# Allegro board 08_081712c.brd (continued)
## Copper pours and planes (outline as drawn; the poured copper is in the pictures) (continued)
DGND on L8_SIG (solid shape): 237.92,84.72 238,84.68 238.01,84.59 238,84.52 237.99,84.45 238.4,84.05 238.81,84.45 238.8,84.52 238.78,84.59 238.8,84.68 238.88,84.72 244.93,84.72 245.02,84.66 245,84.55 244.61,84.15 239.79,84.15 239.67,84.13 239.56,84.06 238.22,82.71 238.15,82.61 238.12,82.49 238.12,80.21 238.15,80.08 238.22,79.98 238.33,79.87 238.35,79.76 238.26,79.69 237.75,79.69 237.6,79.85 237.57,79.94 237.64,80.02 237.87,80.16 237.95,80.41 237.84,80.7 237.55,80.82 237.43,80.8 237.33,80.75 237.23,80.75 237.17,80.84 237.17,81.48 237.23,81.57 237.33,81.57 237.43,81.52 237.55,81.5 237.95,81.91 237.55,82.32 237.43,82.3 237.33,82.25 237.23,82.25 237.17,82.34 237.17,84.22 237.67,84.72
DGND on L8_SIG (solid shape): 205.14,77.42 205.77,77.16 206.41,77.42 207.04,77.16 207.68,77.42 208.31,77.16 208.95,77.42 209.58,77.16 210.22,77.42 210.25,77.4 210.41,77.29 210.58,77.21 210.65,77.13 210.62,77.04 207.34,73.75 207.22,73.73 207.16,73.83 207.16,73.86 206.47,74.15 206.76,73.45 206.78,73.45 206.88,73.39 206.86,73.28 205.86,72.28 199.42,72.28 199.33,72.34 199.35,72.45 204.14,77.24 204.17,77.23 204.34,77.18 204.5,77.16 204.83,77.23 205.1,77.4
DGND on L8_SIG (solid shape): 297.64,103.58 297.73,103.54 297.74,103.45 297.73,103.4 297.71,103.35 296.93,102.56 296.86,102.46 296.84,102.34 296.84,99.83 292.38,95.36 253.95,95.36 253.83,95.34 253.72,95.27 244.55,86.09 237.65,86.09 237.56,86.16 237.58,86.27 238.7,87.39 238.99,87.39 239.08,87.34 239.08,87.23 239.04,87.13 239.02,87.02 239.43,86.62 239.83,87.02 239.82,87.13 239.78,87.23 239.77,87.34 239.86,87.39 244.04,87.39 244.16,87.41 244.27,87.48 252.46,95.67 290.53,95.67 290.65,95.69 290.75,95.76 295.75,100.76 295.85,100.79 295.92,100.72 296.07,100.52 296.3,100.45 296.59,100.57 296.71,100.85 296.63,101.09 296.43,101.24 296.37,101.31 296.4,101.41 296.44,101.45 296.51,101.55 296.53,101.68 296.53,102.62 296.6,102.74 296.62,102.87 296.5,103.16 296.21,103.28 296.2,103.28 296.11,103.34 296.13,103.45 296.26,103.58
DGND on L8_SIG (solid shape): 239.32,101.48 239.32,98.59 239.35,98.47 239.42,98.36 240.12,97.66 240.12,97.56 240.06,97.47 239.95,97.49 239.73,97.71 239.62,97.78 239.5,97.81 239.16,97.81 238.47,98.5 238.44,98.6 238.51,98.67 238.73,98.82 238.81,99.06 238.69,99.35 238.4,99.47 238.16,99.39 238.01,99.17 237.94,99.1 237.84,99.13 236.44,100.53 236.33,100.6 236.21,100.63 233.02,100.63 232.92,100.69 232.94,100.8 233.72,101.57 233.75,101.54 233.87,101.47 234.01,101.45 234.42,101.85 234.01,102.26 233.96,102.26 233.91,102.25 233.82,102.27 233.78,102.35 233.78,102.36 233.82,102.44 233.91,102.46 233.96,102.45 234.01,102.45 234.3,102.57 234.42,102.85 234.33,103.11 234.09,103.25 234.02,103.32 234.04,103.42 234.07,103.45 234.08,103.45 234.32,103.59 234.42,103.85 234.42,103.91 234.41,103.96 234.42,104.04 234.5,104.08 236.72,104.08
DGND on L8_SIG (solid shape): 306.51,106.77 306.58,106.67 306.5,106.58 306.29,106.43 306.21,106.19 306.62,105.78 307.02,106.19 307.02,106.2 307.05,106.28 307.12,106.31 307.85,106.31 307.94,106.25 307.92,106.14 307.85,106.02 307.82,105.87 308.23,105.47 308.64,105.87 308.61,106.02 308.53,106.14 308.52,106.25 308.61,106.31 308.86,106.31 310.3,104.87 310.3,104.82 310.25,104.73 310.15,104.72 310.07,104.75 309.98,104.76 309.84,104.74 309.72,104.67 303.92,104.67 303.8,104.74 303.66,104.76 303.53,104.74 303.42,104.68 303.4,104.67 303.27,104.67 302.33,105.61 302.23,105.68 302.11,105.7 296.92,105.7 296.82,105.77 296.85,105.88 296.95,106.02 296.99,106.19 296.58,106.59 296.18,106.19 296.21,106.02 296.31,105.88 296.34,105.77 296.25,105.7 296.12,105.7 295.22,106.6 295.2,106.71 295.3,106.77
DGND on L8_SIG (solid shape): 18.43,102.06 18.54,102.08 18.61,101.98 18.61,101.1 5.24,87.73 5.17,87.62 5.14,87.5 5.14,65.28 5.17,65.16 5.24,65.05 17.04,53.25 17.04,33.37 16.97,33.25 16.95,33.12 16.96,33.02 17,32.92 17.01,32.84 16.96,32.78 16.91,32.75 16.86,32.71 16.68,32.52 16.66,32.52 16.41,32.38 16.31,32.12 16.43,31.83 16.72,31.71 16.79,31.68 16.94,31.33 17.23,31.21 17.63,31.62 17.23,32.03 17.18,32.02 17.13,32.08 17.22,32.17 20.8,32.17 20.93,32.19 21.03,32.26 28.61,39.84 28.68,39.95 28.7,40.07 28.7,63.68 28.74,63.73 28.81,63.78 28.9,63.75 29.1,63.55 29.1,39.55 16.07,26.53 15.87,26.53 15.78,26.58 15.78,26.69 15.84,26.8 15.85,26.92 15.85,26.99 15.83,27.06 15.83,27.14 15.89,27.19 16.07,27.34 16.14,27.57 16.02,27.86 15.74,27.98 15.49,27.89 15.34,27.68 15.27,27.61 15.18,27.64 14.82,27.99 14.82,54.76 14.8,54.88 14.73,54.98 4.64,65.07 4.64,88.26
DGND on L8_SIG (solid shape): outline of 91 points within 106.31,97.47 122.93,102.54
DGND on L8_SIG (solid shape): outline of 121 points within 205.04,18.95 208.1,27.47
DGND on L8_SIG (solid shape): outline of 303 points within 303.11,100.8 310.3,104.04
DGND on L8_SIG (solid shape): outline of 104 points within 221.69,101.13 233.62,104.15
DGND on L8_SIG (solid shape): outline of 355 points within 131.44,71.67 143.6,81.26
DGND on L8_SIG (solid shape): outline of 101 points within 169.88,60.41 190.9,65.21
DGND on L8_SIG (solid shape): outline of 390 points within 119.81,93.07 132.14,98.63
DGND on L8_SIG (solid shape): outline of 448 points within 66.44,81.1 114.25,99.38
DGND on L8_SIG (solid shape): outline of 434 points within 244.73,76.34 265.87,87.41
DGND on L8_SIG (solid shape): outline of 446 points within 102.75,68.83 122.15,72.81
DGND on L8_SIG (solid shape): outline of 89 points within 172.44,100.63 219.74,102.78
DGND on L8_SIG (solid shape): outline of 742 points within 255.26,58.99 277.13,65.69
DGND on L8_SIG (solid shape): outline of 817 points within 250.55,68.82 272.83,78.07
DGND on L8_SIG (solid shape): outline of 1048 points within 242.85,77.56 320.67,107.48
DGND on L8_SIG (solid shape): outline of 1122 points within 124.18,61.39 171.4,65.21
DGND on L8_SIG (solid shape): outline of 1906 points within 52.34,68.83 143.32,84.39
DGND on L8_SIG (solid shape): outline of 2300 points within 186.86,55.06 253.37,98.86
DGND on L8_SIG (solid shape): outline of 2666 points within 129.34,89.27 295.33,107.77
DGND on L8_SIG (solid shape): outline of 3018 points within 271.21,63.6 362.99,77.66
DGND on L8_SIG (solid shape): outline of 4211 points within 91.21,69.81 216.93,100.13
DGND on TOP: 2.54,194.31 412.75,194.31 412.75,2.54 2.54,2.54 ; 104 cut-outs
DGND on BOTTOM: 217.04,73.28 217.04,70.87 216.79,70.61 215.65,70.61 215.52,70.74 215.52,73.66 215.65,73.79 216.53,73.79
DGND on BOTTOM: 221.61,73.28 221.61,70.87 221.87,70.61 223.01,70.61 223.14,70.74 223.14,73.66 223.01,73.79 222.12,73.79
DGND on BOTTOM: 215.77,84.84 215.77,83.06 218.95,83.06 218.95,84.84
DGND on L2_GND, L4_GND, L5_PWR, L6_PWR, L7_GND, L9_GND: 2.54,194.31 412.75,194.31 412.75,2.54 2.54,2.54
GND_FIELD on BOTTOM (solid shape): outline of 554 points within 126.75,2.54 146.3,15.49
GND_FIELD on BOTTOM (solid shape): outline of 554 points within 253.75,2.54 273.3,15.49
VDDIO on TOP (solid shape): 407.42,105.54 407.29,105.41 405.38,105.41 405.13,105.66 405.13,107.82 405.26,107.95 407.42,107.95
VDDIO on TOP (solid shape): 147.83,36.05 147.83,34.63 147.78,34.58 144.8,34.58 144.8,34.58 144.8,36.1 144.9,36.2 146.29,36.2 146.42,36.32 147.56,36.32
VDDIO on TOP (solid shape): 274.83,36.18 274.83,34.63 274.78,34.58 271.8,34.58 271.8,34.58 271.8,35.97 272.02,36.2 273.29,36.2 273.55,36.45 274.56,36.45
VDDIO on TOP (solid shape): 223.27,111.43 223.27,111.31 223.07,111.11 223.07,111.03 223.07,110.42 223.07,110.29 223.01,110.24 222.25,110.24 222.12,110.11 222.12,109.6 222,109.47 221.61,109.47 221.49,109.6 221.49,111.25 221.68,111.44 223.25,111.44
VDDIO on TOP (solid shape): 300.99,111.43 300.99,111.31 300.79,111.11 300.79,111.03 300.79,110.42 300.79,110.29 300.74,110.24 299.97,110.24 299.85,110.11 299.85,109.6 299.72,109.47 299.34,109.47 299.21,109.6 299.21,111.25 299.4,111.44 300.98,111.44
VDDIO on TOP (solid shape): 16.63,24.11 16.63,22.46 16.44,22.27 14.86,22.27 14.85,22.28 14.85,22.4 15.05,22.6 15.06,22.7 15.06,23.31 15.05,23.42 15.11,23.48 15.87,23.48 15.99,23.6 15.99,24.11 16.12,24.24 16.5,24.24
VDDIO on TOP (solid shape): 384.29,24.11 384.29,22.46 384.1,22.27 382.53,22.27 382.52,22.28 382.52,22.4 382.71,22.6 382.72,22.7 382.72,23.31 382.71,23.42 382.77,23.48 383.53,23.48 383.66,23.6 383.66,24.11 383.79,24.24 384.17,24.24
VDDIO on TOP (solid shape): 229.62,111.43 229.62,111.31 229.42,111.11 229.42,111.03 229.42,110.42 229.42,110.29 229.36,110.24 228.6,110.24 228.47,110.11 228.47,109.6 228.35,109.48 228.23,109.48 228.19,109.47 227.96,109.47 227.84,109.6 227.84,111.25 228.03,111.44 229.6,111.44
VDDIO on TOP (solid shape): 307.34,111.43 307.34,111.31 307.14,111.11 307.14,111.03 307.14,110.42 307.14,110.29 307.09,110.24 306.32,110.24 306.2,110.11 306.2,109.6 306.08,109.48 305.96,109.48 305.91,109.47 305.69,109.47 305.56,109.6 305.56,111.25 305.75,111.44 307.33,111.44
VDDIO on TOP (solid shape): outline of 85 points within 384.56,113.03 397.13,116.2
VDDIO on TOP: 123.95,102.09 123.95,103.74 124.14,103.93 125.72,103.93 125.73,103.92 125.73,103.8 125.53,103.6 125.53,102.78 125.48,102.72 124.71,102.72 124.59,102.6 124.59,102.09 124.46,101.96 124.08,101.96
VDDIO on TOP: 188.09,84.58 188.09,86.23 188.28,86.42 189.85,86.42 189.86,86.41 189.86,86.29 189.67,86.09 189.67,85.27 189.61,85.22 188.85,85.22 188.72,85.09 188.72,84.58 188.59,84.45 188.21,84.45
VDDIO on TOP: 236.63,28.83 236.63,31.09 236.8,31.27 238.25,31.27 238.48,31.04 238.48,30.48 238.33,30.33 237.77,30.33 237.31,29.87 237.31,28.8 237.24,28.73 236.73,28.73
VDDIO on TOP: 182.59,121.54 182.59,122.76 180.83,122.76 180.83,122.28 182.08,122.28 182.08,121.54 182.21,121.41 182.46,121.41
VDDIO on TOP: 112.71,102.15 112.71,103.68 112.97,103.93 114.54,103.93 114.55,103.92 114.55,103.8 114.36,103.6 114.36,102.78 114.3,102.72 113.54,102.72 113.41,102.6 113.41,102.09 113.28,101.96 112.9,101.96
VDDIO on BOTTOM: 188.09,82.66 188.09,81.01 188.29,80.82 189.86,80.82 189.87,80.83 189.87,80.95 189.68,81.14 189.68,81.97 189.62,82.02 188.86,82.02 188.73,82.15 188.73,82.66 188.6,82.78 188.22,82.78
VDDIO on BOTTOM: 120.85,102.19 120.85,103.68 120.58,103.95 119,103.95 118.99,103.94 118.99,103.82 119.19,103.62 119.19,102.8 119.25,102.74 120.01,102.74 120.13,102.62 120.13,102.11 120.26,101.98 120.64,101.98
VDDIO on L5_PWR: 388.8,119.79 388.8,80.26 319.15,80.26 319.15,64.52 388.8,64.52 388.8,20.19 228.5,20.19 228.5,40.18 213.64,40.18 213.64,61.26 204.09,61.26 204.09,65.33 189.59,65.33 189.59,20.19 9.65,20.19 9.65,119.96 37.52,119.96 37.52,103.05 157.77,103.05 177.15,122.43 186.17,122.43 188.81,119.79
(no net) on TOP: 220.34,15.56 220.34,13.78 220.6,13.53 220.6,13.14 219.77,13.14 219.46,13.46 219.46,13.84 219.2,14.1 218.69,14.1 218.57,14.22 218.57,15.37 218.88,15.68 220.22,15.68
(no net) on TOP: 221.49,113.41 221.49,112.01 221.7,111.8 223.07,111.8 223.07,112.47 223.01,112.52 222.25,112.52 222.12,112.65 222.12,113.41 222,113.54 221.61,113.54
(no net) on TOP: 144.75,42.36 144.75,44.43 144.84,44.52 147.7,44.52 147.79,44.43 147.79,42.31 147.79,42.3 144.81,42.3
(no net) on TOP: 16.63,24.11 16.63,22.46 16.44,22.27 14.86,22.27 14.85,22.28 14.85,22.4 15.05,22.6 15.05,23.42 15.11,23.48 15.87,23.48 15.99,23.6 15.99,24.11 16.12,24.24 16.5,24.24
(no net) on TOP: 401.07,131.45 401.07,131.19 407.91,131.19 408.43,131.71 408.43,133.22 407.54,134.11 406.02,134.11 404.88,132.97 403.35,132.97 402.84,132.46 402.84,131.7 402.59,131.45
(no net) on TOP: 345.06,190.88 345.06,185.42 345.82,184.66 355.22,184.66 355.85,184.02 358.78,184.02 359.03,184.28 359.03,190.63 358.27,191.39 345.57,191.39
(no net) on TOP: 395.61,175.64 395.61,175.01 395.68,174.93 397.76,174.93 397.76,175.26 396.49,175.26 396.11,175.64
(no net) on TOP: 227.84,109.6 227.84,111.25 228.03,111.44 229.6,111.44 229.62,111.43 229.62,111.31 229.42,111.11 229.42,110.29 229.36,110.24 228.6,110.24 228.47,110.11 228.47,109.6 228.35,109.47 227.96,109.47
(no net) on TOP: 264.62,46.02 262.95,46.02 262.95,47.64 263.28,47.97 264.28,47.97 264.62,47.64
(no net) on TOP: 392.56,112.01 397.13,112.01 397.13,110.74 395.1,110.74 395.1,108.97 395.48,108.58 397.76,108.58 397.76,108.33 394.46,108.33 394.46,110.74 392.56,110.74
(no net) on TOP: 401.07,174.62 401.07,174.37 405.64,174.37 406.02,174.75 406.02,175.9 405.77,176.15 403.35,176.15 402.84,175.64 402.84,174.88 402.59,174.62
(no net) on TOP: 305.56,109.6 305.56,111.25 305.75,111.44 307.33,111.44 307.34,111.43 307.34,111.31 307.14,111.11 307.14,110.29 307.09,110.24 306.32,110.24 306.2,110.11 306.2,109.6 306.07,109.47 305.69,109.47
(no net) on TOP: 395.61,155.19 395.61,154.56 395.68,154.48 397.76,154.48 397.76,154.81 396.49,154.81 396.11,155.19
(no net) on TOP: 384.56,182.25 384.56,180.09 397.13,180.09 397.13,182.25
(no net) on TOP: 274.83,48.22 274.83,50.1 274.55,50.38 272.01,50.38 271.79,50.15 271.79,48.18 271.79,48.17 274.78,48.17
(no net) on TOP: 402.46,114.05 402.46,111.25 404.37,111.25 404.37,114.05
(no net) on TOP: 272.67,18.92 272.67,24.51 272.54,24.64 269.37,24.64 268.86,24.13 268.86,23.11 267.84,22.1 267.84,20.32 267.08,19.56 259.97,19.56 259.21,20.32 259.21,22.1 258.19,23.11 258.19,24.13 257.68,24.64 254.51,24.64 254.38,24.51 254.38,18.92 255.14,18.16 271.91,18.16
(no net) on TOP: 362.97,183.26 362.97,180.34 363.86,179.45 374.4,179.45 375.16,180.21 375.16,182.88 374.52,183.52 363.22,183.52
(no net) on TOP: 230.76,20.51 232.28,20.51 232.28,20.26 232.03,20 232.03,18.86 231.77,18.61 224.54,18.61 224.54,19.62 229.87,19.62
(no net) on TOP: 221.49,109.6 221.49,111.25 221.68,111.44 223.25,111.44 223.27,111.43 223.27,111.31 223.07,111.11 223.07,110.29 223.01,110.24 222.25,110.24 222.12,110.11 222.12,109.6 222,109.47 221.61,109.47
(no net) on TOP: 401.07,154.18 401.07,153.92 407.79,153.92 408.43,154.57 408.43,155.96 407.54,156.84 406.02,156.84 404.88,155.7 403.35,155.7 402.84,155.19 402.84,154.43 402.59,154.18
(no net) on TOP: 261.03,43.86 259.51,43.86 259.21,44.15 259.21,45.3 259.46,45.54 261.03,45.54
(no net) on TOP: 137.62,46.02 135.95,46.02 135.95,47.64 136.28,47.97 137.28,47.97 137.62,47.64
(no net) on TOP: 405.13,130.68 405.13,128.52 405.38,128.27 407.29,128.27 407.42,128.4 407.42,130.81 405.26,130.81
(no net) on TOP: 395.61,109.6 395.61,108.97 395.68,108.89 397.76,108.89 397.76,109.22 396.49,109.22 396.11,109.6
(no net) on TOP: 402.46,180.09 402.46,177.29 404.37,177.29 404.37,180.09
(no net) on TOP: 145.67,18.92 145.67,24.51 145.54,24.64 142.37,24.64 141.86,24.13 141.86,23.11 140.84,22.1 140.84,20.32 140.08,19.56 132.97,19.56 132.21,20.32 132.21,22.1 131.19,23.11 131.19,24.13 130.68,24.64 127.51,24.64 127.38,24.51 127.38,18.92 128.14,18.16 144.91,18.16
(no net) on TOP: 384.56,161.8 384.56,159.25 384.93,158.88 388.1,158.88 388.86,159.64 397.13,159.64 397.13,161.8
(no net) on TOP: 231.9,24.45 231.9,20.76 230.76,20.76 230.5,21.02 230.5,23.18 230,23.69 224.54,23.69 224.54,24.7 231.65,24.7
(no net) on TOP: 139.4,43.11 139.4,44.78 141.11,44.78 141.36,44.54 141.36,43.4 141.07,43.11
(no net) on TOP: 221.87,11.62 224.03,11.62 224.16,11.49 224.16,10.6 224.41,10.35 229.23,10.35 229.23,11.11 228.47,11.87 221.87,11.87
(no net) on TOP: 134.03,43.86 132.51,43.86 132.21,44.15 132.21,45.3 132.46,45.54 134.03,45.54
(no net) on TOP: 405.13,107.82 405.13,105.66 405.38,105.41 407.29,105.41 407.42,105.54 407.42,107.95 405.26,107.95
(no net) on TOP: 299.21,113.41 299.21,112.01 299.43,111.8 300.79,111.8 300.79,112.47 300.74,112.52 299.97,112.52 299.85,112.65 299.85,113.41 299.72,113.54 299.34,113.54
(no net) on TOP: 401.07,108.58 401.07,108.33 407.79,108.33 408.43,108.98 408.43,110.36 407.54,111.25 406.02,111.25 404.88,110.11 403.35,110.11 402.84,109.6 402.84,108.84 402.59,108.58
(no net) on TOP: 220.6,11.87 220.6,10.99 220.09,10.48 220.09,5.4 219.58,4.89 216.03,4.89 215.52,5.4 215.52,7.3 216.15,7.94 218.31,7.94 218.82,8.45 218.82,11.37 219.33,11.87
(no net) on TOP: 266.4,43.11 266.4,44.78 268.11,44.78 268.36,44.54 268.36,43.4 268.07,43.11
(no net) on TOP: 384.56,139.06 384.56,136.39 384.8,136.14 387.97,136.14 388.74,136.91 397.13,136.91 397.13,139.06
(no net) on TOP: 384.29,20.3 384.29,21.7 384.08,21.91 382.71,21.91 382.71,21.25 382.77,21.19 383.53,21.19 383.66,21.06 383.66,20.3 383.79,20.17 384.17,20.17
(no net) on TOP: 392.56,134.87 397.13,134.87 397.13,133.6 395.1,133.6 395.1,131.83 395.48,131.45 397.76,131.45 397.76,131.19 394.46,131.19 394.46,133.6 392.56,133.6
(no net) on TOP: 402.46,136.91 402.46,134.11 404.37,134.11 404.37,136.91
(no net) on TOP: 384.56,116.2 384.56,113.53 385.05,113.03 387.72,113.03 388.74,114.05 397.13,114.05 397.13,116.2
(no net) on TOP: 229.23,9.59 224.66,9.59 224.66,6.03 225.04,5.65 228.73,5.65 229.23,6.16
(no net) on TOP: 392.56,157.61 397.13,157.61 397.13,156.34 395.1,156.34 395.1,154.56 395.48,154.18 397.76,154.18 397.76,153.92 394.46,153.92 394.46,156.34 392.56,156.34
(no net) on TOP: 384.29,24.11 384.29,22.46 384.1,22.27 382.53,22.27 382.52,22.28 382.52,22.4 382.71,22.6 382.71,23.42 382.77,23.48 383.53,23.48 383.66,23.6 383.66,24.11 383.79,24.24 384.17,24.24
(no net) on TOP: 402.46,159.64 402.46,156.84 404.37,156.84 404.37,159.64
(no net) on TOP: 405.13,173.86 405.13,171.7 405.38,171.45 407.29,171.45 407.42,171.58 407.42,173.99 405.26,173.99
(no net) on TOP: 337.95,190.63 337.95,188.85 337.44,188.34 328.68,188.34 328.04,187.71 328.04,184.15 328.8,183.39 340.87,183.39 341.38,183.9 341.38,190.63 341.12,190.88 338.2,190.88
(no net) on TOP: 395.61,132.46 395.61,131.83 395.68,131.75 397.76,131.75 397.76,132.08 396.49,132.08 396.11,132.46
(no net) on TOP: 147.83,34.63 147.83,36.05 147.56,36.32 146.42,36.32 146.29,36.2 144.9,36.2 144.8,36.1 144.8,34.58 144.8,34.58 147.78,34.58
(no net) on TOP: 305.56,113.41 305.56,112.01 305.78,111.8 307.14,111.8 307.14,112.47 307.09,112.52 306.32,112.52 306.2,112.65 306.2,113.41 306.07,113.54 305.69,113.54
(no net) on TOP: 392.56,178.05 397.13,178.05 397.13,176.78 395.1,176.78 395.1,175.01 395.48,174.62 397.76,174.62 397.76,174.37 394.46,174.37 394.46,176.78 392.56,176.78
(no net) on TOP: 227.96,23.43 229.87,23.43 230.12,23.18 230.12,20.26 229.74,19.88 227.96,19.88 227.71,20.13 227.71,23.18
(no net) on TOP: 360.05,190.75 360.05,186.82 360.43,186.44 367.03,186.44 368.05,187.45 368.05,190.5 367.16,191.39 360.68,191.39
(no net) on TOP: 147.83,48.22 147.83,50.1 147.55,50.38 145.01,50.38 144.79,50.15 144.79,48.18 144.79,48.17 147.78,48.17
(no net) on TOP: 16.63,20.3 16.63,21.7 16.41,21.91 15.05,21.91 15.05,21.25 15.11,21.19 15.87,21.19 15.99,21.06 15.99,20.3 16.12,20.17 16.5,20.17
(no net) on TOP: 405.13,153.42 405.13,151.26 405.38,151 407.29,151 407.42,151.13 407.42,153.54 405.26,153.54
(no net) on TOP: 299.21,109.6 299.21,111.25 299.4,111.44 300.98,111.44 300.99,111.43 300.99,111.31 300.79,111.11 300.79,110.29 300.74,110.24 299.97,110.24 299.85,110.11 299.85,109.6 299.72,109.47 299.34,109.47
(no net) on TOP: 221.87,11.37 223.77,11.37 223.9,11.24 223.9,10.6 223.27,10.6 222.76,11.11 221.87,11.11
(no net) on TOP: 227.84,113.41 227.84,112.01 228.05,111.8 229.42,111.8 229.42,112.47 229.36,112.52 228.6,112.52 228.47,112.65 228.47,113.41 228.35,113.54 227.96,113.54
(no net) on TOP: 274.83,34.63 274.83,36.18 274.56,36.45 273.55,36.45 273.29,36.2 272.02,36.2 271.8,35.97 271.8,34.58 271.8,34.58 274.78,34.58
(no net) on TOP: 271.75,42.36 271.75,44.43 271.84,44.52 274.7,44.52 274.79,44.43 274.79,42.31 274.79,42.3 271.81,42.3
(no net) on BOTTOM: 236.98,72.14 236.98,67.69 239.27,67.69 239.27,72.14
(no net) on BOTTOM: 96.77,59.18 96.77,57.02 96.52,56.77 94.61,56.77 94.49,56.9 94.49,58.67 95.12,59.31 96.65,59.31
(no net) on BOTTOM: 236.35,63.37 231.77,63.37 231.77,62.1 233.81,62.1 233.81,60.32 233.43,59.94 231.14,59.94 231.14,59.69 234.44,59.69 234.44,62.1 236.35,62.1
(no net) on BOTTOM: 2.54,194.31 412.75,194.31 412.75,2.54 2.54,2.54 ; 3 cut-outs
(no net) on BOTTOM: 109.98,72.14 109.98,67.69 112.27,67.69 112.27,72.14
(no net) on BOTTOM: 99.44,65.41 99.44,62.61 97.54,62.61 97.54,65.41
(no net) on BOTTOM: 223.77,59.18 223.77,57.02 223.52,56.77 221.61,56.77 221.49,56.9 221.49,58.67 222.12,59.31 223.65,59.31
(no net) on BOTTOM: 236.35,72.14 236.35,65.41 231.77,65.41 231.77,72.14
(no net) on BOTTOM: 106.3,60.96 106.3,60.32 106.22,60.25 104.14,60.25 104.14,60.58 105.41,60.58 105.79,60.96
(no net) on BOTTOM: 109.35,63.37 104.78,63.37 104.78,62.1 106.81,62.1 106.81,60.32 106.43,59.94 104.14,59.94 104.14,59.69 107.44,59.69 107.44,62.1 109.35,62.1
(no net) on BOTTOM: 233.3,60.96 233.3,60.32 233.22,60.25 231.14,60.25 231.14,60.58 232.41,60.58 232.79,60.96
(no net) on BOTTOM: 227.84,59.94 227.84,59.69 223.01,59.69 223.01,60.96 223.52,61.47 225.55,61.47 226.06,60.96 226.06,60.2 226.31,59.94
(no net) on BOTTOM: 109.35,72.14 109.35,65.41 104.78,65.41 104.78,72.14
(no net) on BOTTOM: 100.84,59.94 100.84,59.69 96.01,59.69 96.01,60.96 96.52,61.47 98.55,61.47 99.06,60.96 99.06,60.2 99.31,59.94
(no net) on BOTTOM: 273.3,2.54 253.75,2.54 253.75,15.49 273.3,15.49
(no net) on BOTTOM: 226.44,65.41 226.44,62.61 224.54,62.61 224.54,65.41
(no net) on BOTTOM: 146.3,2.54 126.75,2.54 126.75,15.49 146.3,15.49
(no net) on L3_SIG, L8_SIG: 2.54,194.31 412.75,194.31 412.75,2.54 2.54,2.54
(no net) on L5_PWR: 190.25,38.16 190.25,64.69 203.45,64.69 203.45,60.64 213,60.64 213,39.52 227.71,39.52 227.71,20.13 220.22,20.13 220.22,25.72 215.01,25.72 215.01,34.61 209.3,34.61 209.3,39.69 205.49,39.69 205.49,38.16
(no net) on L5_PWR: 96.77,116.08 96.77,108.2 117.47,108.2 117.47,115.44 115.7,117.22 97.92,117.22
(no net) on L5_PWR: 227.71,19.49 227.71,4.89 224.28,4.89 224.28,11.75 192.41,11.75 192.41,6.54 190.25,6.54 190.25,37.53 206.12,37.53 206.12,39.05 208.66,39.05 208.66,34.04 214.38,34.04 214.38,25.08 219.65,25.08 219.65,19.49
(no net) on L5_PWR: 205.99,10.73 205.99,4.89 218.57,4.89 218.57,10.73
(no net) on L6_PWR: 201.71,24.07 201.71,17.08 210.18,17.08 210.18,24.07
_N20 on TOP (solid shape): outline of 84 points within 127.38,18.16 145.67,24.64
_N50 on TOP (solid shape): outline of 84 points within 254.38,18.16 272.67,24.64
_N114 on BOTTOM: 219.96,77.85 219.96,77.1 220.85,76.21 220.85,73.91 219.58,73.91 219.58,77.85
_N115 on BOTTOM: 218.69,77.85 218.69,77.09 217.8,76.2 217.8,73.91 219.07,73.91 219.07,77.85
_N116 on BOTTOM: 219.71,80.26 222.88,80.26 223.65,79.5 223.65,75.56 223.01,74.93 221.23,74.93 221.23,76.2 222.5,76.2 222.88,76.58 222.88,77.98 222.5,78.36 221.49,78.36 220.22,79.63 219.71,79.63
_N117 on BOTTOM: 218.44,77.85 218.44,77.22 217.42,76.2 217.42,74.93 216.15,74.93 216.15,77.72 216.28,77.85
_N763 on TOP (solid shape): 396.49,154.81 397.76,154.81 397.76,154.48 395.68,154.48 395.61,154.56 395.61,155.19 396.11,155.19
_N767 on TOP (solid shape): 397.13,156.34 395.1,156.34 395.1,154.56 395.48,154.18 395.48,154.18 395.53,154.13 397.76,154.13 397.76,153.92 394.46,153.92 394.46,156.34 392.56,156.34 392.56,157.61 397.13,157.61
_N780 on L5_PWR (solid shape): outline of 1312 points within 96.77,108.2 117.47,117.22
_N2536 on BOTTOM (solid shape): 109.35,62.1 107.44,62.1 107.44,59.69 104.14,59.69 104.14,59.89 106.37,59.89 106.42,59.94 106.43,59.94 106.81,60.32 106.81,62.1 104.78,62.1 104.78,63.37 109.35,63.37
_N2541 on BOTTOM (solid shape): 106.3,60.32 106.22,60.25 104.14,60.25 104.14,60.58 105.41,60.58 105.79,60.96 106.3,60.96
_N2566 on BOTTOM (solid shape): 236.35,62.1 234.44,62.1 234.44,59.69 231.14,59.69 231.14,59.89 233.37,59.89 233.42,59.94 233.43,59.94 233.81,60.32 233.81,62.1 231.77,62.1 231.77,63.37 236.35,63.37
_N2571 on BOTTOM (solid shape): 233.3,60.32 233.22,60.25 231.14,60.25 231.14,60.58 232.41,60.58 232.79,60.96 233.3,60.96
E70_3V3 on TOP (solid shape): 232.28,20.26 232.03,20 232.03,18.86 231.77,18.61 224.54,18.61 224.54,19.62 229.87,19.62 230.76,20.51 232.28,20.51
E70_3V3 on TOP (solid shape): 220.34,15.56 220.34,13.78 220.6,13.53 220.6,13.14 219.77,13.14 219.46,13.46 219.46,13.84 219.2,14.1 218.69,14.1 218.57,14.22 218.57,15.37 218.88,15.68 220.22,15.68
E70_3V3 on TOP (solid shape): 229.23,6.16 228.73,5.65 227.1,5.65 227.01,5.7 227.01,5.8 227.1,6.04 227.13,6.29 226.06,7.35 224.99,6.29 225.03,6 225.15,5.73 225.16,5.72 225.16,5.65 225.04,5.65 224.66,6.03 224.66,9.59 229.23,9.59
E70_3V3 on L5_PWR (solid shape): outline of 7214 points within 190.25,4.89 227.71,39.05
E70_VDDCORE on L6_PWR (solid shape): outline of 1290 points within 201.71,17.08 210.18,24.07
JTAG_1V8 on TOP (solid shape): 231.9,24.45 231.9,20.77 230.76,20.77 230.5,21.02 230.5,23.18 230,23.69 224.54,23.69 224.54,24.7 231.65,24.7
JTAG_IO on TOP (solid shape): 230.12,23.18 230.12,20.26 229.74,19.88 227.96,19.88 227.71,20.13 227.71,23.18 227.96,23.43 229.87,23.43
JTAG_IO on L5_PWR (solid shape): outline of 2930 points within 190.25,20.13 227.71,64.69
UNNAMED_4_ADLT8609_I14_BST on TOP (solid shape): 396.49,175.26 397.76,175.26 397.76,174.93 395.68,174.93 395.61,175.01 395.61,175.64 396.11,175.64
UNNAMED_4_ADLT8609_I14_SW on TOP (solid shape): 397.13,176.78 395.1,176.78 395.1,175.01 395.48,174.62 395.48,174.62 395.53,174.57 397.76,174.57 397.76,174.37 394.46,174.37 394.46,176.78 392.56,176.78 392.56,178.05 397.13,178.05
UNNAMED_4_ADLT8609_I48_BST on TOP (solid shape): 396.49,132.08 397.76,132.08 397.76,131.75 395.68,131.75 395.61,131.83 395.61,132.46 396.11,132.46
UNNAMED_4_ADLT8609_I48_SW on TOP (solid shape): 397.13,133.6 395.1,133.6 395.1,131.83 395.48,131.45 395.48,131.45 395.53,131.39 397.76,131.39 397.76,131.19 394.46,131.19 394.46,133.6 392.56,133.6 392.56,134.87 397.13,134.87
UNNAMED_4_ADLT8609_I60_BST on TOP (solid shape): 396.49,109.22 397.76,109.22 397.76,108.89 395.68,108.89 395.61,108.97 395.61,109.6 396.11,109.6
UNNAMED_4_ADLT8609_I60_SW on TOP (solid shape): 397.13,110.74 395.1,110.74 395.1,108.97 395.48,108.58 395.48,108.58 395.53,108.53 397.76,108.53 397.76,108.33 394.46,108.33 394.46,110.74 392.56,110.74 392.56,112.01 397.13,112.01
UNNAMED_4_CAP_I21_N2 on TOP (solid shape): outline of 101 points within 328.04,183.39 341.38,190.88
UNNAMED_4_CHOKE4P_I25_N3 on TOP (solid shape): 368.05,190.5 368.05,187.45 367.03,186.44 360.43,186.44 360.05,186.82 360.05,190.75 360.68,191.39 367.16,191.39
UNNAMED_4_CHOKE4P_I25_N4 on TOP (solid shape): 359.03,190.63 359.03,184.28 358.78,184.02 355.85,184.02 355.22,184.66 345.82,184.66 345.06,185.42 345.06,190.88 345.57,191.39 358.27,191.39
UNNAMED_12_ADLT8618_I115_BST on TOP (solid shape): 223.8,10.6 223.27,10.6 222.76,11.11 221.87,11.11 221.87,11.26 223.8,11.26
UNNAMED_12_ADLT8618_I115_SW on TOP (solid shape): 223.96,11.85 224.03,11.85 224.1,11.85 224.17,11.87 228.47,11.87 229.23,11.11 229.23,10.35 224.41,10.35 224.16,10.6 224.16,11.49 224.03,11.62 221.87,11.62 221.87,11.87 223.88,11.87
USB_5V on TOP (solid shape): outline of 89 points within 215.52,4.89 220.6,11.87
USB_5V on L5_PWR (solid shape): outline of 447 points within 205.99,4.89 218.57,10.73

Small or netless copper shapes (teardrops, artwork), in the pictures only: 19 on BOTTOM, 11 on L8_SIG

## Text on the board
Ref Des/Assembly Bottom: MATE ENTRY
Ref Des/Silkscreen Bottom: PUSHBUTTON A_2 | PUSHBUTTON A_1 | PUSHBUTTON B_2 | PUSHBUTTON B_1 | RESET | 08-081712 REV C Z
User.Comments: PCB | PAN HEAD SCREW | MPN=97790403111 | STANDOFF | MPN=CBMFTS205A | HEX NUT | MPN=4688 | BOTTOM SIDE | TOP SIDE | POLARITY | MARKING | CHAMFER | SOM BOARD | SOM CARRIER BOARD (BR-081712) | SEE DETAIL E (4 PLACES) | SIDE OF THE BOARD. | 2.    REPAIRS PER IPC-7711/21(LATEST REVISION) ARE ALLOWED. | 1.    BOARD ACCEPTABILITY PER ANALOG DEVICES, INC. SPECIFICATION | TST00119 (LATEST REVISION). | 5.    SEE CRYSTAL OSCILLATOR PIN 1 DETAILS: | 7.    SMOOTHEN EDGES AND FREE FROM BURRS AFTER DEPANELIZATION PROCESS. | 9.    INSTALL JUMPER SHUNTS (M000389) ON THE FOLLOWING LOCATIONS: | 10.   REFER TO DETAIL E FOR THE MOUNTING DETAILS OF THE SOM BOARDS. | 3.    REPAIRS ARE NOT ALLOWED IN SOLDERMASK FREE AREAS ON EITHER | 4.    SEE DETAIL A FOR D12. | 6.    SINGULATE BOARD AFTER ASSEMBLY PROCESS | 8.    RoHS COMPLIANCE: ASSEMBLY VENDOR SHOULD ASSURE COMPLIANCE | ASSEMBLY NOTES: | WITH LEAD-FREE AND RoHS PCB ASSEMBLY STANDARDS (EU RoHS | DIRECTIVE 2002/95/EC). | THE REQUIRED MOUNTING PARTS ARE LISTED IN THE PSPEC BOM. | A. P36: PINS 1-2 | A. SEE DETAIL B FOR CRYSTALS Y1 AND Y2. | B. SEE DETAIL C FOR Y3. | C. SEE DETAIL D FOR Y6. | 598-XXXX-307F_ASSY-DETAIL | BOTTOM VIEW | SCALE: NONE | DETAIL A | DETAIL B | DETAIL C | DETAIL D | ECSXXXX-ASSY-DETAIL | ABM8AIG-ASSY-DETAIL | KCXXXXZ-ASSY-DETAIL | DETAIL E | SOM_BRD_MOUNTING_ASSY_DETAILS
Ref Des/Assembly Top: MATE_ENTRY | 1 | MATE ENTRY | C | A
Ref Des/Silkscreen Top: 1 | C | A | EEPROM | SWITCH | SOM A | MLB | IO1 | IO2 | IO3 | CLK | SIG | DAT | JTAG DAISY | CHAIN CTRL | JTAG SOMA/ | SOMB SWITCH | A2B_1 | EV-SOMCRR2-EZKIT | A2B_2 | JTAG | A2B_3 | A2B_4 | 12VIN
PAGE_OUTLINE: A | B | C | INITIAL RELEASE | REVISION PER ECR-125349 | REVISION PER ECR-130699 | 30SEP24 | 22SEP25 | 08MAY26 | D. HARRINGTON | CUSTOMER EVAL Z
BODY_CENTER: FAB NOTES REVISION: NOVEMBER 21 2022 | 8.   IMPEDANCE REQUIREMENTS: IF NO STACKUP IS DEFINED, THE VENDOR IS ALLOWED TO ADJUST THE DIELECTRIC | 13.  PLATING SPECIFICATION: | 1.   DIMENSIONS ARE IN INCHES (EXCEPT WHERE NOTED). | ALL DOCUMENTS & SPECIFICATIONS REFERRED TO BELOW SHOULD BE THE LATEST REVISIONS. | 2.  BOARD MATERIAL:(USE CHECKED ITEMS) | 3.   ALL LAMINATES & BONDING MATERIALS SHOULD BE SELECTED FROM IPC-4101 OR IPC-4103,(TG>170 DEGC TD>300 DEGC) | 4.   REFER TO IPC-6010 SERIES, CLASS 2 FOR FABRICATION. | 5.   REFER TO LAMINATION DIAGRAM FOR OVERALL BOARD THICKNESS, TOLERANCE APPLIES AFTER ALL LAMINATION AND PLATING | 6.   BOW & TWIST NOT TO EXCEED 0.0075 INCHES (0.75%) PER LINEAR INCH AND SHOULD BE MEASURED PER IPC-TM-650, METHOD 2.4.22. | 7.   ACCEPTABILITY PER ADI SPECIFICATION TST00115. | 9.   FILLET OPTIONS TO ENHANCE RELIABILITY AT PAD JUNCTIONS WHERE SPACING PERMITS. | 10.  THIEVING: | 11.  LAYER TO LAYER REGISTRATION SHALL BE WITHIN 0.003 INCHES. | 12.  DRILL SIZES ARE FINISHED HOLE SIZES. ALL HOLES SHALL BE LOCATED WITHIN 0.005 INCHES DTP,UNLESS SPECIFIED. | 14.  SURFACE FINISH: | 15.  SOLDERMASK: | 16.  APPLY SILKSCREEN TO BOTH SIDES USING A NON-CONDUCTIVE, EPOXY BASED INK PER ARTWORK. | (X) WHITE | ( ) OTHER | PROCESSES. FINISHED THICKNESS MEASURED FROM TOP COPPER TO BOTTOM COPPER. | (X)  ISOLA 370HR OR S1000-2 OR IT180 OR EQUIVALENT | ( )  ISOLA-FR408HR OR EQUIVALENT | ( )  ISOLA IS410 | ( )  MEGTRON 6 | ( )  NELCO-4000-13 | ( )  ROGERS 4350B | ( ) ROGERS 3003 | ( ) ARLON 85N | ( ) EM370D | ( ) OTHER : | ( ) FILLETS ALLOWED | (X) FILLETS NOT ALLOWED | ( ) VENDOR MAY ADD THIEVING TO COMPENSATE FOR LOW COPPER DENSITY AREAS MAINTAINING A MINIMUM | (X) VENDOR MAY NOT ADD THIEVING TO COMPENSATE FOR LOW COPPER DENSITY AREAS. | (X) LPI | ( ) OTHER_________ | COLOR | (X) GREEN | HINDER PROPER SOLDER WICKING. BARREL RELIEF ON SOLDERMASK ALLOWED IN UNFILLED VIA IN PAD HOLES. | (X) REFER TO LAMINATION DIAGRAM FOR FINISHED COPPER WEIGHT/THICKNESS REQUIRMENTS | (X) IMMERSION GOLD (ENIG) 1.58-3.94 MICRO INCHES OVER 118-236 MICRO INCHES MIN. OF ELECTROLESS NICKEL PER IPC-4552 | ( ) OSP (ORGANIC SOLDERABILITY PRESERVATIVE) | ( ) IMMERSION SILVER | ( ) SOFT WIRE BONDABLE GOLD 30-50 MICRO INCHES OF SOFT WIRE | ( ) EDGE CONNECTOR FINGERS ARE TO BE PLATED WITH 100 MICRO-INCHES(.0001") OF LOW STRESS | THICKNESS & TRACE WIDTHS TO MEET THE IMPEDANCE REQUIREMENT. IF SPECIFIED, THE VENDOR MUST | TRACE WIDTH & SPACING THAT IMPACT THE REQUIREMENTS MUST HAVE WRITTEN APPROVAL FROM ADI. | MINIMUM BARREL PLATING OF 0.001 INCHES. PLATED HOLES SHALL NOT BE ROUGH OR IRREGULAR SO AS TO | SOLDERMASK OVER BARE COPPER OR BARE GOLD (BOTH SIDES) TO MEET IPC-SM-840. | IF PRESENT,DO NOT MODIFY SOLDERMASK DEFINED PADS (MASK OPENINGS LESS THAN COPPER PAD) WITHOUT APPROVAL. | MEET THE REQUIREMENTS LISTED IN THE IMPEDANCE TABLE. ANY ADJUSTMENT MADE TO THE DEFINED STACKUP, | UL FLAMMABILITY RATING 94V-0. BOARD MATERIAL & CONSTRUCTION SHALL MEET THE REQUIREMENTS OF UL796/UL796F. | BONDABLE GOLD OVER 100-150 MICRO INCHES OF NICKEL | NICKEL UNDER 30 MICRO-INCHES (.00003') OF GOLD | 0.100 INCH CLEARANCE FROM ALL COPPER FEATURES, | THE STARTING COPPER WEIGHT/THICKNESS CAN VARY AS LONG AS THE FINISHED COPPER | WEIGHT/THICKNESS IS NOT LESS THAN THE SPECIFIED VALUE. | UNLESS OTHERWISE SPECIFIED | HOMOGENOUS MATERIALS IN THIS BOARD SHALL BE COMPLAINT WITH THE EU DIRECTIVE 2002/95/EC | WORKMANSHIP SHALL CONFORM TO IPC-A-600, CLASS 2. | 21.  INTENTIONAL SHORTS: | 17.  FINAL ELECTRICAL TEST TO BE PERFORMED USING PROVIDED IPC-D-356A NETLIST OR ODB++ FORMAT FILE. | 22.  PEMNUTS: | 23.  MANUFACTURER TO ETCH/STAMP WITH PERMANENT NON-CONDUCTIVE INK | ON SECONDARY SIDE UNLESS OTHERWISE SPECIFIED: | 18.  A TIME DOMAIN REFLECTOMETER REPORT (TDR) FOR EACH IMPEDANCE CONTROLLED LAYER & A CERTIFICATE | 19.  IF PRESENT, ALL BLIND/BURIED VIAS WITH AN ASPECT RATIO <1:1 TO BE PLATED SHUT WITH COPPER WHEN | 20.  FOR VIA FILL INFORMATION REFER TO DRILL CHART: | 24. PANELIZATION: | 25.  MINIMUM DESIGN LINE WIDTH IS .004 INCHES. | 26.  MINIMUM DESIGN SPACING IS .004 INCHES. | IS ACCEPTABLE, ALL OTHER INSTANCES MUST BE REPORTED. | IF AN INTENTIONAL SHORT REPORT IS SUPPLIED AND DOES NOT MATCH THE FAB DATA THEN | THE PCB SHALL HAVE A VERIFICATION STAMP. | (X)  NON-CONDUCTIVE EPOXY FILL ALL 0.004 INCHES DRILLED VIAS | ( )  COPPER FILL ALL 0.XXXX INCHES DRILLED VIAS | ( ) PEMNUTS TO BE INSTALLED BY FABRICATOR | ( ) PEMNUTS NOT TO BE INSTALLED BY FABRICATOR | (X) NOT APPLICABLE | USED AS VIA-IN-PAD OR AS A STACKED VIA. BLIND/BURIED VIAS WITH AN ASPECT RATIO >1:1 TO BE FILLED | A. UL CODE-FLAMMABILITY RATING FOR THOSE APPROVED MATERIALS(IF APPLICABLE) | B. DATE CODE | C. LOT NUMBER | D. MANUFACTURER LOGO | BOARDS TO BE SHIPPED IN ARRAY AND KEPT INTACT | PANEL TO BE SUBJECTED TO CUSTOMERS APPROVAL | PANEL SOLDER PASTE STENCIL GERBER TO BE PROVIDED TO ANALOG | CAN'T BE PERFORMED BECAUSE THE TRACE LENGTH IS TOO SHORT ON THE OUTER LAYERS AT THE PIN ESCAPES | ADI APPROVAL IS REQUIRED. | OF COMPLIANCE SHALL BE PROVIDED BY VENDOR AT TIME OF SHIPMENT. INSTANCES WHERE TDR TESTING | WITH NON-CONDUCTIVE EPOXY. | 10-LAYER STACKUP | NOTES: | TOOLING: | FINISH: | MATERIAL: | TESTING: | MISCELLANEOUS:
DIMENSION: LABEL PLACEMENT INFORMATION | HALF SIZE LABELS ARE | AVAILABLE IN THE LIBRARY | PLACE WHEELIE BIN LOGO | TO SUIT THE LAYOUT. | PLACE ROHS COMPLIANT LOGO | TO SUIT THE LAYOUT OR | DELETE IF NOT REQ'D. | PLACE CHINA ROHS COMPLIANT | LOGO TO SUIT THE LAYOUT OR | DIA MAX/SEE NOTE 20 | 1.THE BOARD SIZE CAN BE ADJUSTED TO SUIT THE APPLICATION. | 2.THE MOUNTING HOLES CAN BE MOVED/REMOVED TO SUIT THE APPLICATION. | 3.THE FIDUCIALS CAN BE MOVED TO SUIT THE APPLICATION. | 4.ADJUST THE DIMENSIONS TO SUIT THE APPLICATION. | 5.ADD THE CORRECT LAYER STACKUP ON FAB2 BASED ON THE NO OF LAYERS ON THE PCB. | 6.THE ROHS COMPLIANT AND WHEELIE BIN LOGO'S CAN BE MOVED TO THE DESIRED LOCATION. | HALF SIZE VERSIONS OF THE LABELS ARE AVAILABLE IN THE LIBRARY. | NOTES FOR TEMPLATE USAGE. | _ | " " | (REF) | DIA MAX | GENERIC D-SIZE TEMPLATE BR-067706A
User.24: L2 GND | 08-      -07
User.25: L3 SIG | 08-      -08
User.26: L4 GND | 08-      -09
User.27: L5 PWR | 08-      -10
User.28: L6 PWR | 08-      -11
User.29: L7 GND | 08-      -12
User.30: L8 SIG | 08-      -13
User.31: L9 GND | 08-      -14
User.35: ETHERNET | SPDIF | CAN | P14 | DAC | SOM | P11 | P12 | P13 | DA | HEADERS | P15 | ADC | P16 | POWER
User.45: FIGURE | SIZE | 4.0 | 10.0 | 16.0 | 29.0 | 35.0 | 40.0 | 45.0 | 50.0 | 60.0 | 63.0 | 75.0 | 91.0 | 120.0 | 43.0 | 83.0 | 98.0 | 110.0 | 125.0 | 126.0 | 48.0x24.0 | 118.0x67.0 | PLATED | NON-PLATED | FINISHED HOLES IN MILS | ALL UNITS ARE IN MILS | QTY | 54 | 6380 | 14 | 30 | 57 | 76 | 200 | 90 | 6 | 2 | 3 | 16 | 4 | 8 | 20 | 7000 | TOLERANCE/NOTES | TOTAL HOLES: | 1
